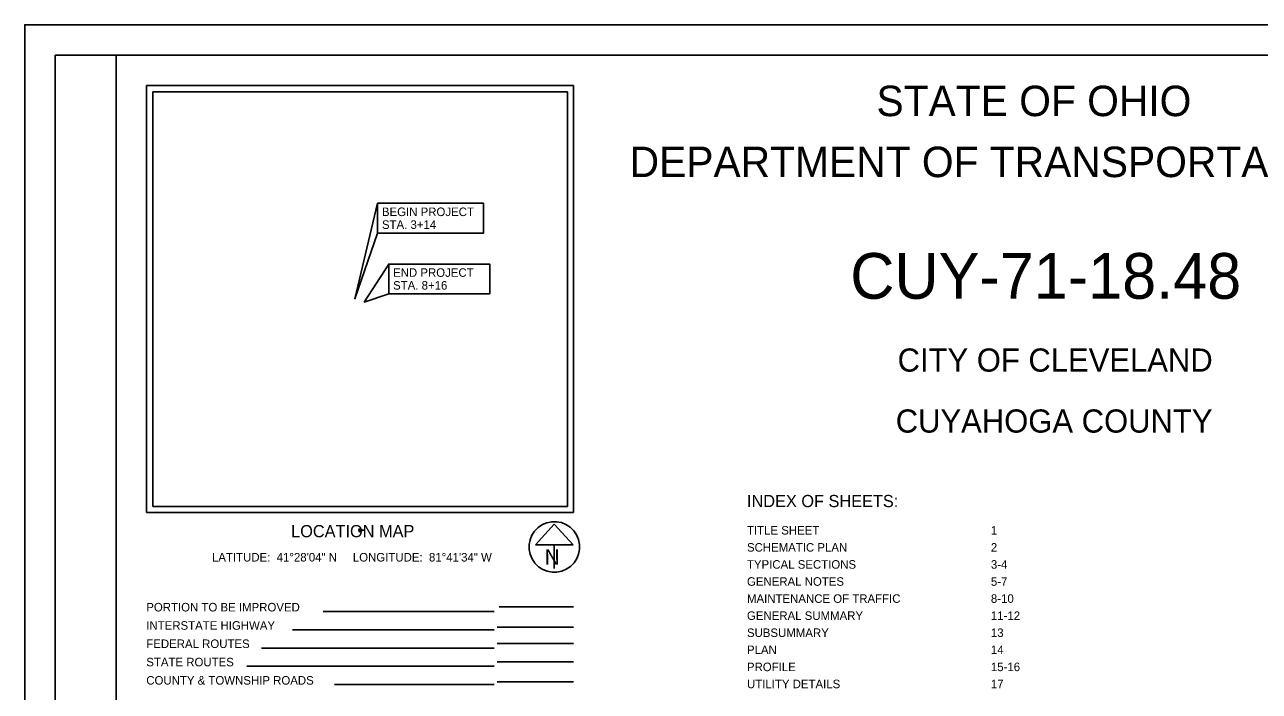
# Model space of a CAD drawing. Extents: x 0 to 34, y 0 to 22.
# Drawn here: x 0 to 20.25, y 11.07 to 22 of the extents above; entities that cross this region are included whole.
import ezdxf

# ---------------------------------------------------------------- set-up
doc = ezdxf.new("R2010")
doc.units = 0
for name, color, linetype in [('SH_Border', 7, 'Continuous'), ('SH_Cut_Line', 7, 'Continuous'), ('SH_Data', 7, 'Continuous'), ('SH_Text', 7, 'Continuous'), ('SN_P_Truss_Overhead', 7, 'Continuous')]:
    doc.layers.add(name, color=color, linetype=linetype)

msp = doc.modelspace()

# ---------------------------------------------------------------- linework, layer by layer
at = {"layer": 'SH_Border'}
for points in [[(0.5, 21.5), (1.5, 21.5), (1.5, 0.5), (0.5, 0.5)], [(1.5, 21.5), (33.5, 21.5), (33.5, 0.5), (1.5, 0.5)]]:
    msp.add_lwpolyline(points, close=True, dxfattribs=at)
at = {"layer": 'SH_Cut_Line'}
msp.add_lwpolyline([(0, 0), (34, 0), (34, 22), (0, 22)], close=True, dxfattribs=at)
at = {"layer": 'SH_Data'}
for p, q in [((2, 21), (9, 21)), ((2, 21), (2, 14)), ((2.1, 20.9), (2.1, 14.1)), ((2.1, 20.9), (8.9, 20.9)), ((8.9, 20.9), (8.9, 14.1)), ((9, 21), (9, 14)), ((2, 14), (9, 14)), ((2.1, 14.1), (8.9, 14.1)), ((8.685, 13.809), (8.377, 13.468)), ((8.992, 13.468), (8.685, 13.809)), ((8.377, 13.468), (8.992, 13.468)), ((8.685, 13.468), (8.685, 13.081)), ((8.685, 13.435), (8.685, 13.435)), ((8.685, 13.435), (8.685, 13.435)), ((7.7, 12.377), (4.894, 12.377)), ((7.783, 12.455), (9, 12.455)), ((7.7, 12.077), (4.39, 12.077)), ((9, 12.121), (7.75, 12.121)), ((7.7, 11.777), (3.885, 11.777)), ((9, 11.849), (7.75, 11.849)), ((9, 11.549), (7.75, 11.549)), ((7.7, 11.477), (3.645, 11.477)), ((7.7, 11.177), (5.078, 11.177)), ((9, 11.222), (7.75, 11.222))]:
    msp.add_line(p, q, dxfattribs=at)
msp.add_arc((8.685, 13.435), 0.415, 129.7798, 129.7633, dxfattribs=at)
at = {"layer": 'SH_Text'}
for points in [[(5.788, 18.581), (5.416, 17.504), (5.788, 19.071)], [(5.788, 18.581), (7.524, 18.581), (7.524, 19.071), (5.788, 19.071)], [(5.971, 18.075), (5.568, 17.452), (5.971, 17.585)], [(5.971, 17.585), (7.626, 17.585), (7.626, 18.075), (5.971, 18.075)]]:
    msp.add_lwpolyline(points, close=True, dxfattribs=at)
at = {"layer": 'SN_P_Truss_Overhead'}
for p, q in [((5.477, 13.708), (5.529, 13.708)), ((5.503, 13.708), (5.565, 13.708))]:
    msp.add_line(p, q, dxfattribs=at)
msp.add_circle((5.503, 13.708), 0.026, dxfattribs=at)

# ---------------------------------------------------------------- texts
at = {"layer": 'SH_Data'}
msp.add_text('N', height=0.25, dxfattribs=at).set_placement((8.529, 13.144))
at = {"layer": 'SH_Text'}
for s, height, p in [('STATE OF OHIO', 0.5, (13.968, 20.5)), ('DEPARTMENT OF TRANSPORTATION', 0.5, (9.92, 19.5)), ('BEGIN PROJECT', 0.14, (5.858, 18.861)), ('STA. 3+14', 0.14, (5.858, 18.651)), ('CUY-71-18.48', 0.75, (13.538, 17.505)), ('END PROJECT', 0.14, (6.041, 17.865)), ('STA. 8+16', 0.14, (6.041, 17.655)), ('CITY OF CLEVELAND', 0.38, (14.314, 16.31)), ('CUYAHOGA COUNTY', 0.38, (14.283, 15.31)), ('INDEX OF SHEETS:', 0.2, (11.844, 14.088)), ('LOCATION MAP', 0.2, (4.369, 13.594)), ('TITLE SHEET', 0.14, (11.844, 13.638)), ('1', 0.14, (15.844, 13.638)), ('SCHEMATIC PLAN', 0.14, (11.844, 13.358)), ('2', 0.14, (15.844, 13.358)), ('LATITUDE:  41°28\'04" N     LONGITUDE:  81°41\'34" W', 0.14, (3.071, 13.196)), ('TYPICAL SECTIONS', 0.14, (11.844, 13.078)), ('3-4', 0.14, (15.844, 13.078)), ('GENERAL NOTES', 0.14, (11.844, 12.798)), ('5-7', 0.14, (15.844, 12.798)), ('MAINTENANCE OF TRAFFIC', 0.14, (11.844, 12.518)), ('8-10', 0.14, (15.844, 12.518)), ('PORTION TO BE IMPROVED', 0.14, (1.994, 12.377)), ('GENERAL SUMMARY', 0.14, (11.844, 12.238)), ('11-12', 0.14, (15.844, 12.238)), ('INTERSTATE HIGHWAY', 0.14, (1.994, 12.077)), ('SUBSUMMARY', 0.14, (11.844, 11.958)), ('13', 0.14, (15.844, 11.958)), ('FEDERAL ROUTES', 0.14, (1.994, 11.777)), ('PLAN', 0.14, (11.844, 11.678)), ('14', 0.14, (15.844, 11.678)), ('STATE ROUTES', 0.14, (1.994, 11.477)), ('PROFILE', 0.14, (11.844, 11.398)), ('15-16', 0.14, (15.844, 11.398)), ('COUNTY & TOWNSHIP ROADS', 0.14, (1.994, 11.177)), ('UTILITY DETAILS', 0.14, (11.844, 11.118)), ('17', 0.14, (15.844, 11.118))]:
    msp.add_text(s, height=height, dxfattribs=at).set_placement(p)
at = {"layer": 'SN_P_Truss_Overhead'}
for s, p in [('P.1', (5.5, 13.698)), ('1', (5.502, 13.714)), ('Drawing', (5.535, 13.714)), ('CUSTOM 98:1', (5.535, 13.698))]:
    msp.add_text(s, height=0.00328, dxfattribs=at).set_placement(p)

doc.saveas('drawing.dxf')
